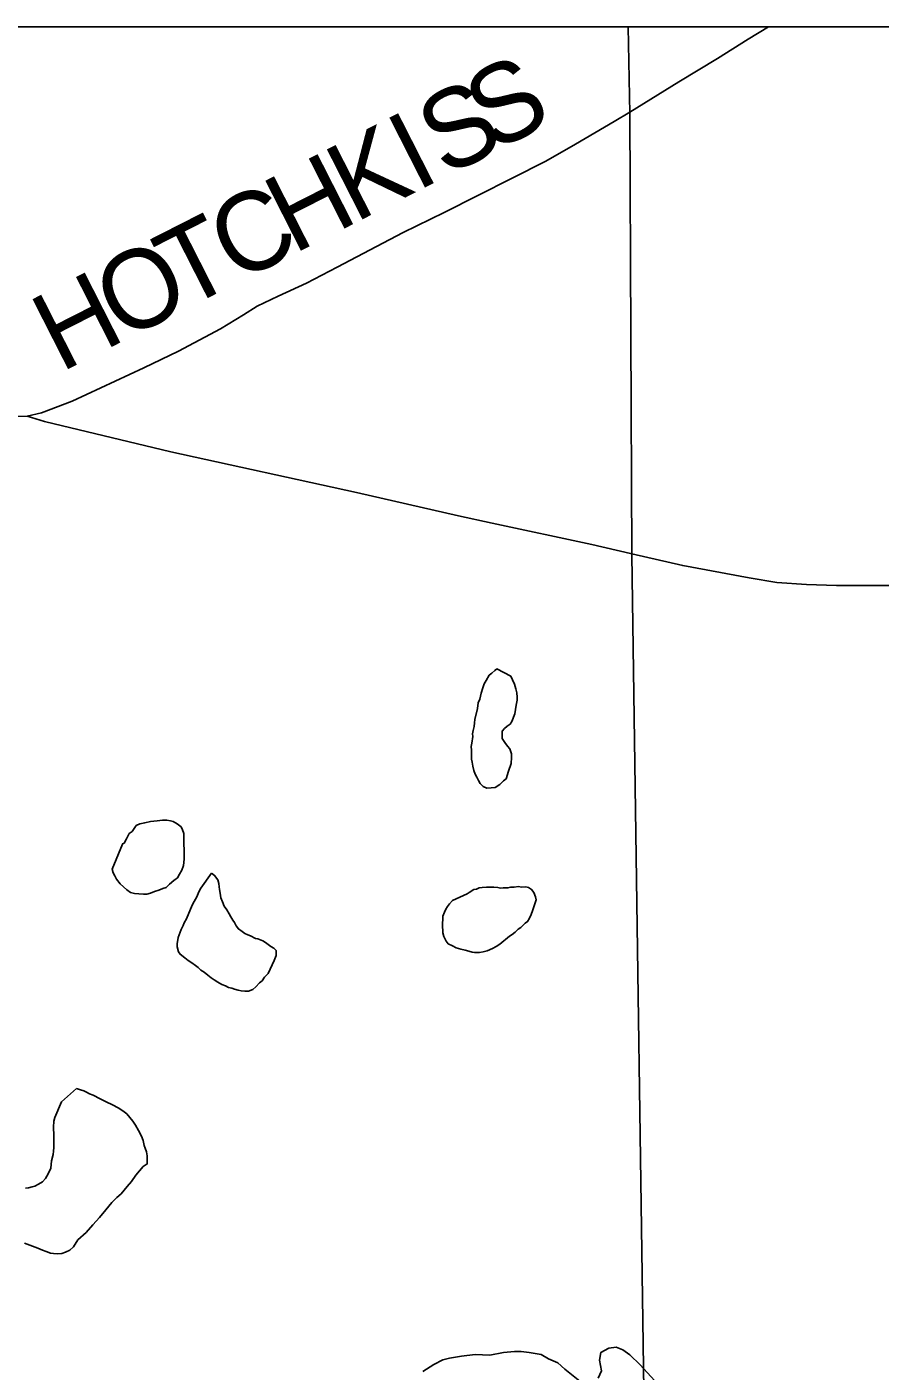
# Model space of a CAD drawing. Extents: x 10.6 to 44.6, y -2.6 to 23.4.
# Drawn here: x 14.801 to 15.419, y 21.353 to 22.327 of the extents above; entities that cross this region are included whole.
import ezdxf

# ---------------------------------------------------------------- set-up
doc = ezdxf.new("R2010")
doc.units = 0
for name, color, linetype in [('GM_X_County', 7, 'Continuous'), ('GM_X_Minor_Lake', 7, 'Continuous'), ('GM_X_Township', 7, 'Continuous'), ('GM_X_Township_Road', 7, 'Continuous'), ('GM_X_Township_Road_Text', 7, 'Continuous')]:
    doc.layers.add(name, color=color, linetype=linetype)

msp = doc.modelspace()

# ---------------------------------------------------------------- linework, layer by layer
at = {"layer": 'GM_X_County'}
msp.add_lwpolyline([(20.00331, 15.53022), (20.00331, 22.32669), (13.20331, 22.32669), (13.20331, 15.52669), (19.84134, 15.52669)], dxfattribs=at)
at = {"layer": 'GM_X_Minor_Lake'}
for points in [[(15.14135, 21.86196), (15.13986, 21.86079), (15.13762, 21.85884), (15.13575, 21.85728), (15.13355, 21.85343), (15.13207, 21.85112), (15.131, 21.84806), (15.12994, 21.84424), (15.12889, 21.84003), (15.1278, 21.83735), (15.12713, 21.83316), (15.1254, 21.82514), (15.12507, 21.82285), (15.12475, 21.82018), (15.12405, 21.81713), (15.12372, 21.81484), (15.12376, 21.81294), (15.12311, 21.80799), (15.12277, 21.8057), (15.12283, 21.80304), (15.12289, 21.80038), (15.12293, 21.79849), (15.12297, 21.79659), (15.1234, 21.79432), (15.12384, 21.79129), (15.12467, 21.78827), (15.12549, 21.78562), (15.12668, 21.78337), (15.12787, 21.78111), (15.12906, 21.77886), (15.13138, 21.77663)], [(15.14135, 21.86196), (15.13986, 21.86079), (15.13762, 21.85884), (15.13575, 21.85728), (15.13355, 21.85343), (15.13207, 21.85112), (15.131, 21.84806), (15.12994, 21.84424), (15.12889, 21.84003), (15.1278, 21.83735), (15.12713, 21.83316), (15.1254, 21.82514), (15.12507, 21.82285), (15.12475, 21.82018), (15.12405, 21.81713), (15.12372, 21.81484), (15.12376, 21.81294), (15.12311, 21.80799), (15.12277, 21.8057), (15.12283, 21.80304), (15.12289, 21.80038), (15.12293, 21.79849), (15.12297, 21.79659), (15.1234, 21.79432), (15.12384, 21.79129), (15.12467, 21.78827), (15.12549, 21.78562), (15.12668, 21.78337), (15.12787, 21.78111), (15.12906, 21.77886), (15.13138, 21.77663), (15.13407, 21.77555), (15.13711, 21.77562), (15.14015, 21.77606), (15.14353, 21.77804), (15.14613, 21.78075), (15.148, 21.78231), (15.14979, 21.78767), (15.15157, 21.79341), (15.15186, 21.7976), (15.1518, 21.80026), (15.15058, 21.80403), (15.14902, 21.80589), (15.14706, 21.80851), (15.14509, 21.81151), (15.14504, 21.81417), (15.14498, 21.81683), (15.14684, 21.81877), (15.14871, 21.82033), (15.15096, 21.82189), (15.15206, 21.82382), (15.15423, 21.82919), (15.15523, 21.83567), (15.15592, 21.8391), (15.15587, 21.84138), (15.1558, 21.84442), (15.15498, 21.84744), (15.15414, 21.85084), (15.15256, 21.85385), (15.15136, 21.85648), (15.14135, 21.86196)], [(15.13138, 21.77663), (15.13407, 21.77555), (15.13711, 21.77562), (15.14015, 21.77606), (15.14353, 21.77804), (15.14613, 21.78075), (15.148, 21.78231), (15.14979, 21.78767), (15.15157, 21.79341), (15.15186, 21.7976), (15.1518, 21.80026), (15.15058, 21.80403), (15.14902, 21.80589), (15.14706, 21.80851), (15.14509, 21.81151), (15.14504, 21.81417), (15.14498, 21.81683), (15.14684, 21.81877), (15.14871, 21.82033), (15.15096, 21.82189), (15.15206, 21.82382), (15.15423, 21.82919), (15.15523, 21.83567), (15.15592, 21.8391), (15.15587, 21.84138), (15.1558, 21.84442), (15.15498, 21.84744), (15.15414, 21.85084), (15.15256, 21.85385), (15.15136, 21.85648), (15.14135, 21.86196)], [(14.87018, 21.73485), (14.86258, 21.71683), (14.8634, 21.71419), (14.86459, 21.71193), (14.86577, 21.70968), (14.86851, 21.70632), (14.87084, 21.70409), (14.87317, 21.70186), (14.87587, 21.70002), (14.87893, 21.69932), (14.88198, 21.69901), (14.88541, 21.6987), (14.88769, 21.69875), (14.89034, 21.69957), (14.89335, 21.70078), (14.89638, 21.7016), (14.8994, 21.70281), (14.90166, 21.70362), (14.90427, 21.70595), (14.90726, 21.70868), (14.90988, 21.71064), (14.91134, 21.71333), (14.91319, 21.71603), (14.91426, 21.71947), (14.91459, 21.72176), (14.91491, 21.72443), (14.91484, 21.72784), (14.91463, 21.73772), (14.91457, 21.74038), (14.91452, 21.74266), (14.9137, 21.7453), (14.91252, 21.74755), (14.90981, 21.74977), (14.90673, 21.75123), (14.90481, 21.75194), (14.90214, 21.75227), (14.8991, 21.7522), (14.89531, 21.75174), (14.89037, 21.75125), (14.88621, 21.7504), (14.8828, 21.74956), (14.88016, 21.74837), (14.87721, 21.74413), (14.87496, 21.74256), (14.87314, 21.73872), (14.87131, 21.73564), (14.87017, 21.73523), (14.87018, 21.73485)], [(14.91426, 21.71947), (14.91459, 21.72176), (14.91491, 21.72443), (14.91484, 21.72784), (14.91463, 21.73772), (14.91457, 21.74038), (14.91452, 21.74266), (14.9137, 21.7453), (14.91252, 21.74755), (14.90981, 21.74977), (14.90673, 21.75123), (14.90481, 21.75194), (14.90214, 21.75227), (14.8991, 21.7522), (14.89531, 21.75174), (14.89037, 21.75125), (14.88621, 21.7504), (14.8828, 21.74956), (14.88016, 21.74837), (14.87721, 21.74413), (14.87496, 21.74256), (14.87314, 21.73872), (14.87131, 21.73564), (14.87017, 21.73523), (14.87018, 21.73485)], [(14.87018, 21.73485), (14.86258, 21.71683), (14.8634, 21.71419), (14.86459, 21.71193), (14.86577, 21.70968), (14.86851, 21.70632), (14.87084, 21.70409), (14.87317, 21.70186), (14.87587, 21.70002), (14.87893, 21.69932), (14.88198, 21.69901), (14.88541, 21.6987), (14.88769, 21.69875), (14.89034, 21.69957), (14.89335, 21.70078), (14.89638, 21.7016), (14.8994, 21.70281), (14.90166, 21.70362), (14.90427, 21.70595), (14.90726, 21.70868), (14.90988, 21.71064), (14.91134, 21.71333), (14.91319, 21.71603), (14.91426, 21.71947)], [(14.93454, 21.71383), (14.92678, 21.70302), (14.92532, 21.70033), (14.92387, 21.69688), (14.92204, 21.69342), (14.92058, 21.69073), (14.91661, 21.68077), (14.91476, 21.67807), (14.91404, 21.67615), (14.91259, 21.67308), (14.91115, 21.66925), (14.91043, 21.66733), (14.90977, 21.66276), (14.90981, 21.66048), (14.91065, 21.65708), (14.91183, 21.6552), (14.91531, 21.65262), (14.91763, 21.65077), (14.92033, 21.64893), (14.92303, 21.64709), (14.92497, 21.64561), (14.92691, 21.64375), (14.92922, 21.64228), (14.93193, 21.64006), (14.93426, 21.63821), (14.93657, 21.63674), (14.93927, 21.6349), (14.94197, 21.63344), (14.94465, 21.63236), (14.94696, 21.63127), (14.94926, 21.63056), (14.95117, 21.62984), (14.95385, 21.62914), (14.95614, 21.62881), (14.95881, 21.62849), (14.96147, 21.62854), (14.96449, 21.62975)], [(14.93454, 21.71383), (14.92678, 21.70302), (14.92532, 21.70033), (14.92387, 21.69688), (14.92204, 21.69342), (14.92058, 21.69073), (14.91661, 21.68077), (14.91476, 21.67807), (14.91404, 21.67615), (14.91259, 21.67308), (14.91115, 21.66925), (14.91043, 21.66733), (14.90977, 21.66276), (14.90981, 21.66048), (14.91065, 21.65708), (14.91183, 21.6552), (14.91531, 21.65262), (14.91763, 21.65077), (14.92033, 21.64893), (14.92303, 21.64709), (14.92497, 21.64561), (14.92691, 21.64375), (14.92922, 21.64228), (14.93193, 21.64006), (14.93426, 21.63821), (14.93657, 21.63674), (14.93927, 21.6349), (14.94197, 21.63344), (14.94465, 21.63236), (14.94696, 21.63127), (14.94926, 21.63056), (14.95117, 21.62984), (14.95385, 21.62914), (14.95614, 21.62881), (14.95881, 21.62849), (14.96147, 21.62854), (14.96449, 21.62975), (14.96673, 21.6317), (14.96934, 21.63441), (14.9712, 21.63598), (14.97305, 21.63868), (14.97565, 21.64139), (14.98002, 21.65061), (14.98146, 21.65444), (14.98139, 21.65786), (14.97982, 21.65972), (14.97752, 21.66081), (14.97559, 21.66229), (14.97365, 21.66377), (14.97173, 21.66486), (14.96827, 21.66631), (14.96636, 21.66665), (14.9629, 21.66847), (14.96098, 21.66919), (14.95868, 21.67028), (14.95674, 21.67176), (14.95404, 21.6736), (14.95247, 21.67584), (14.95128, 21.6781), (14.9501, 21.67997), (14.94853, 21.68222), (14.94734, 21.68447), (14.94576, 21.68748), (14.9438, 21.6901), (14.94259, 21.69311), (14.94138, 21.69612), (14.94093, 21.69953), (14.94049, 21.70218), (14.94007, 21.70407), (14.94002, 21.70635), (14.93921, 21.70899), (14.93685, 21.71236), (14.93454, 21.71383)], [(14.96449, 21.62975), (14.96673, 21.6317), (14.96934, 21.63441), (14.9712, 21.63598), (14.97305, 21.63868), (14.97565, 21.64139), (14.98002, 21.65061), (14.98146, 21.65444), (14.98139, 21.65786), (14.97982, 21.65972), (14.97752, 21.66081), (14.97559, 21.66229), (14.97365, 21.66377), (14.97173, 21.66486), (14.96827, 21.66631), (14.96636, 21.66665), (14.9629, 21.66847), (14.96098, 21.66919), (14.95868, 21.67028), (14.95674, 21.67176), (14.95404, 21.6736), (14.95247, 21.67584), (14.95128, 21.6781), (14.9501, 21.67997), (14.94853, 21.68222), (14.94734, 21.68447), (14.94576, 21.68748), (14.9438, 21.6901), (14.94259, 21.69311), (14.94138, 21.69612), (14.94093, 21.69953), (14.94049, 21.70218), (14.94007, 21.70407), (14.94002, 21.70635), (14.93921, 21.70899), (14.93685, 21.71236), (14.93454, 21.71383)], [(15.11974, 21.69886), (15.10919, 21.69407), (15.10695, 21.69175), (15.10547, 21.68981), (15.10437, 21.68789), (15.10328, 21.68559), (15.1022, 21.6829), (15.10225, 21.68063), (15.10193, 21.67758), (15.10199, 21.67492), (15.10204, 21.67264), (15.10208, 21.67074), (15.1029, 21.6681), (15.10449, 21.66471), (15.10605, 21.66285), (15.10913, 21.6614), (15.11182, 21.65993), (15.11527, 21.65887), (15.11832, 21.65817), (15.121, 21.65748), (15.1233, 21.65676), (15.12521, 21.65642), (15.12863, 21.6565), (15.13128, 21.65694), (15.13431, 21.65776), (15.13808, 21.65937), (15.14071, 21.66094), (15.14334, 21.66252), (15.15044, 21.66837), (15.15232, 21.66956), (15.15457, 21.67112), (15.1568, 21.67345), (15.15867, 21.67463), (15.16165, 21.67774), (15.16353, 21.67892), (15.16463, 21.68084), (15.16609, 21.68391), (15.16717, 21.6866), (15.16895, 21.69234), (15.16966, 21.69463), (15.16923, 21.6969), (15.16802, 21.69991), (15.16645, 21.70216), (15.16414, 21.70363), (15.16223, 21.70397), (15.15919, 21.7039), (15.1569, 21.70423), (15.15387, 21.70379), (15.15121, 21.70373), (15.14931, 21.70331), (15.14589, 21.70323), (15.14399, 21.70319), (15.14208, 21.70353), (15.13903, 21.70384), (15.13637, 21.70379), (15.13371, 21.70373), (15.13066, 21.70366), (15.12839, 21.70323), (15.12651, 21.70243), (15.12461, 21.70201), (15.12123, 21.70004), (15.11974, 21.69886)], [(15.11974, 21.69886), (15.10919, 21.69407), (15.10695, 21.69175), (15.10547, 21.68981), (15.10437, 21.68789), (15.10328, 21.68559), (15.1022, 21.6829), (15.10225, 21.68063), (15.10193, 21.67758), (15.10199, 21.67492), (15.10204, 21.67264), (15.10208, 21.67074), (15.1029, 21.6681), (15.10449, 21.66471), (15.10605, 21.66285), (15.10913, 21.6614), (15.11182, 21.65993), (15.11527, 21.65887), (15.11832, 21.65817), (15.121, 21.65748), (15.1233, 21.65676), (15.12521, 21.65642), (15.12863, 21.6565), (15.13128, 21.65694), (15.13431, 21.65776), (15.13808, 21.65937), (15.14071, 21.66094), (15.14334, 21.66252), (15.15044, 21.66837), (15.15232, 21.66956), (15.15457, 21.67112)], [(15.15457, 21.67112), (15.1568, 21.67345), (15.15867, 21.67463), (15.16165, 21.67774), (15.16353, 21.67892), (15.16463, 21.68084), (15.16609, 21.68391), (15.16717, 21.6866), (15.16895, 21.69234), (15.16966, 21.69463), (15.16923, 21.6969), (15.16802, 21.69991), (15.16645, 21.70216), (15.16414, 21.70363), (15.16223, 21.70397), (15.15919, 21.7039), (15.1569, 21.70423), (15.15387, 21.70379), (15.15121, 21.70373), (15.14931, 21.70331), (15.14589, 21.70323), (15.14399, 21.70319), (15.14208, 21.70353), (15.13903, 21.70384), (15.13637, 21.70379), (15.13371, 21.70373), (15.13066, 21.70366), (15.12839, 21.70323), (15.12651, 21.70243), (15.12461, 21.70201), (15.12123, 21.70004), (15.11974, 21.69886)], [(14.83692, 21.55803), (14.82586, 21.54846), (14.82116, 21.53696), (14.82046, 21.53428), (14.82017, 21.5301), (14.8203, 21.52402), (14.82037, 21.5206), (14.82043, 21.51794), (14.82048, 21.51528), (14.82016, 21.51262), (14.81983, 21.51033), (14.81879, 21.50575), (14.81814, 21.50041), (14.81633, 21.49619), (14.8145, 21.49274), (14.81227, 21.49041), (14.80926, 21.48882), (14.80663, 21.48724), (14.80474, 21.48682), (14.80209, 21.48601), (14.79981, 21.48595)], [(14.82895, 21.43947), (14.83196, 21.44106), (14.83457, 21.44339), (14.83789, 21.44841), (14.84386, 21.45385), (14.84869, 21.45928), (14.85352, 21.4647), (14.85797, 21.47012), (14.86242, 21.47554), (14.86615, 21.47904), (14.86913, 21.48176), (14.87136, 21.48447), (14.87358, 21.48718), (14.87655, 21.49066), (14.87987, 21.4953), (14.88507, 21.50149), (14.88807, 21.50345), (14.88795, 21.50915), (14.8875, 21.51218), (14.88668, 21.51482), (14.88588, 21.5167), (14.88504, 21.52049), (14.88383, 21.5235), (14.88184, 21.52764), (14.87948, 21.53139), (14.87752, 21.53438), (14.87556, 21.537), (14.87322, 21.53961), (14.87051, 21.54183), (14.86704, 21.54403), (14.86281, 21.54622), (14.8582, 21.5484), (14.85396, 21.55059), (14.84896, 21.55314), (14.84628, 21.55422), (14.84397, 21.55531), (14.84205, 21.55641), (14.83975, 21.55712), (14.83745, 21.55783), (14.83692, 21.55803)], [(14.79914, 21.44604), (14.80489, 21.44389), (14.80873, 21.44245), (14.81218, 21.44101), (14.81487, 21.43992), (14.81793, 21.43885), (14.82023, 21.43852), (14.82327, 21.43821), (14.82631, 21.43865), (14.82895, 21.43947)], [(15.20372, 21.34415), (15.19045, 21.35477), (15.18552, 21.35932), (15.17868, 21.36235), (15.17337, 21.36538), (15.16465, 21.36689), (15.15895, 21.36764), (15.15402, 21.36764), (15.14606, 21.36687), (15.13619, 21.36496), (15.12557, 21.36533), (15.1157, 21.36418), (15.10698, 21.36265), (15.10204, 21.3615), (15.09559, 21.35807), (15.08763, 21.35313)], [(15.25532, 21.34649), (15.24508, 21.35787), (15.23749, 21.36508), (15.23256, 21.36887), (15.22763, 21.37076), (15.22232, 21.37), (15.21663, 21.36695), (15.21549, 21.36125), (15.217, 21.35366), (15.21473, 21.34834)]]:
    msp.add_lwpolyline(points, dxfattribs=at)
at = {"layer": 'GM_X_Township'}
msp.add_line((19.97013, 22.32669), (15.23634, 22.32669), dxfattribs=at)
for points in [[(15.23634, 22.32669), (13.20331, 22.32669), (13.20331, 20.82169)], [(13.20331, 20.82169), (14.24806, 20.83852), (14.89269, 20.85364), (15.25451, 20.86458), (15.25138, 21.08076), (15.24934, 21.22179), (15.23889, 21.94438), (15.23748, 22.26398), (15.23634, 22.32669)], [(15.23634, 22.32669), (15.23748, 22.26398), (15.23889, 21.94438), (15.24934, 21.22179), (15.25138, 21.08076), (15.25451, 20.86458), (16.64382, 20.89834), (17.62302, 20.91969), (18.6416, 20.92773), (19.65809, 20.9527), (20.00331, 20.95729)]]:
    msp.add_lwpolyline(points, dxfattribs=at)
at = {"layer": 'GM_X_Township_Road'}
for points in [[(15.24253, 22.26817), (15.27295, 22.28693), (15.30107, 22.3039), (15.32337, 22.31771), (15.33786, 22.32669)], [(14.7927, 22.0445), (14.80119, 22.04474), (14.81137, 22.04717), (14.83367, 22.05565), (14.85452, 22.06535), (14.88555, 22.07989), (14.91076, 22.09177), (14.94107, 22.10802), (14.95779, 22.1182), (14.96773, 22.1245), (14.98276, 22.13177), (15.00337, 22.14123), (15.02567, 22.15262), (15.05404, 22.16765), (15.07343, 22.17783), (15.10301, 22.19238), (15.1767, 22.22947), (15.19815, 22.24165), (15.22616, 22.25808), (15.23746, 22.26505), (15.24253, 22.26817)], [(15.238, 21.94539), (15.20992, 21.95189), (15.13792, 21.96741), (15.11343, 21.97274), (15.03949, 21.98947), (14.90519, 22.01904), (14.81355, 22.04086), (14.80119, 22.04474)], [(15.44216, 21.92232), (15.38713, 21.92232), (15.36555, 21.92304), (15.34398, 21.9245), (15.32386, 21.92789), (15.27586, 21.93662), (15.23889, 21.94518), (15.238, 21.94539)]]:
    msp.add_lwpolyline(points, dxfattribs=at)

# ---------------------------------------------------------------- texts
at = {"layer": 'GM_X_Township_Road_Text'}
for s, rotation, p in [('S', 27.66039, (15.13856, 22.23548)), ('S', 27.01787, (15.1038, 22.21774)), ('I', 26.96341, (15.08295, 22.20714)), ('K', 26.95603, (15.03837, 22.18447)), ('H', 26.95603, (14.9938, 22.1618)), ('C', 26.95778, (14.95221, 22.14065)), ('T', 26.95896, (14.91432, 22.12138)), ('O', 26.95603, (14.86975, 22.09871)), ('H', 26.95603, (14.82518, 22.07605))]:
    msp.add_text(s, height=0.05682, rotation=rotation, dxfattribs=at).set_placement(p)

doc.saveas('drawing.dxf')
